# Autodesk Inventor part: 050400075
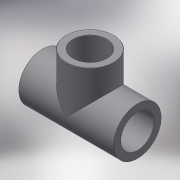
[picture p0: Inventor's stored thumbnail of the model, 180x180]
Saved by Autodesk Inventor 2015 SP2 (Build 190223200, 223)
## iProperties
Created: 2017-10
Part Number: 050400075
Material: Generic
Description: PLASSON TEE-CEMENT PVC 75
Document SubType Name: Modeling
Designer: KIM
Density: 1 g/cm^3
Appearance: Default
Author: KIM
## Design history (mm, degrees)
derived "050400.ipt"
feature "Solid1::050400.ipt"
feature "Solid2::050400.ipt"
tag "TaggingFeature1"
body "Solid1"
other parameters: "d0" = 169, "d2" = 44, "d4" = 75, "d5" = 67.5, "d7" = 0.75, "d8" = 44, "d9" = 85, "d11" = 75, "d12" = 67.5, "d15" = 0, "d17" = 0, "d18" = 75, "d19" = 67.5, "d20" = 75, "d21" = 44, "d22" = 0, "d23" = 44, "d24" = 0.75, "d_" = 75, "H_" = 169, "l_" = 44, "Z_" = 41
